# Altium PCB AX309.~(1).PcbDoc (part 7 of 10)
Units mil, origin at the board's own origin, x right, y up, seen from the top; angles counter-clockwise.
Board outline 5185 x 3614 mil, 4 copper layers (Top Layer, GND, Mid-Layer 1, Bottom Layer); 191 components, 352 nets, 1106 pads, 425 vias.
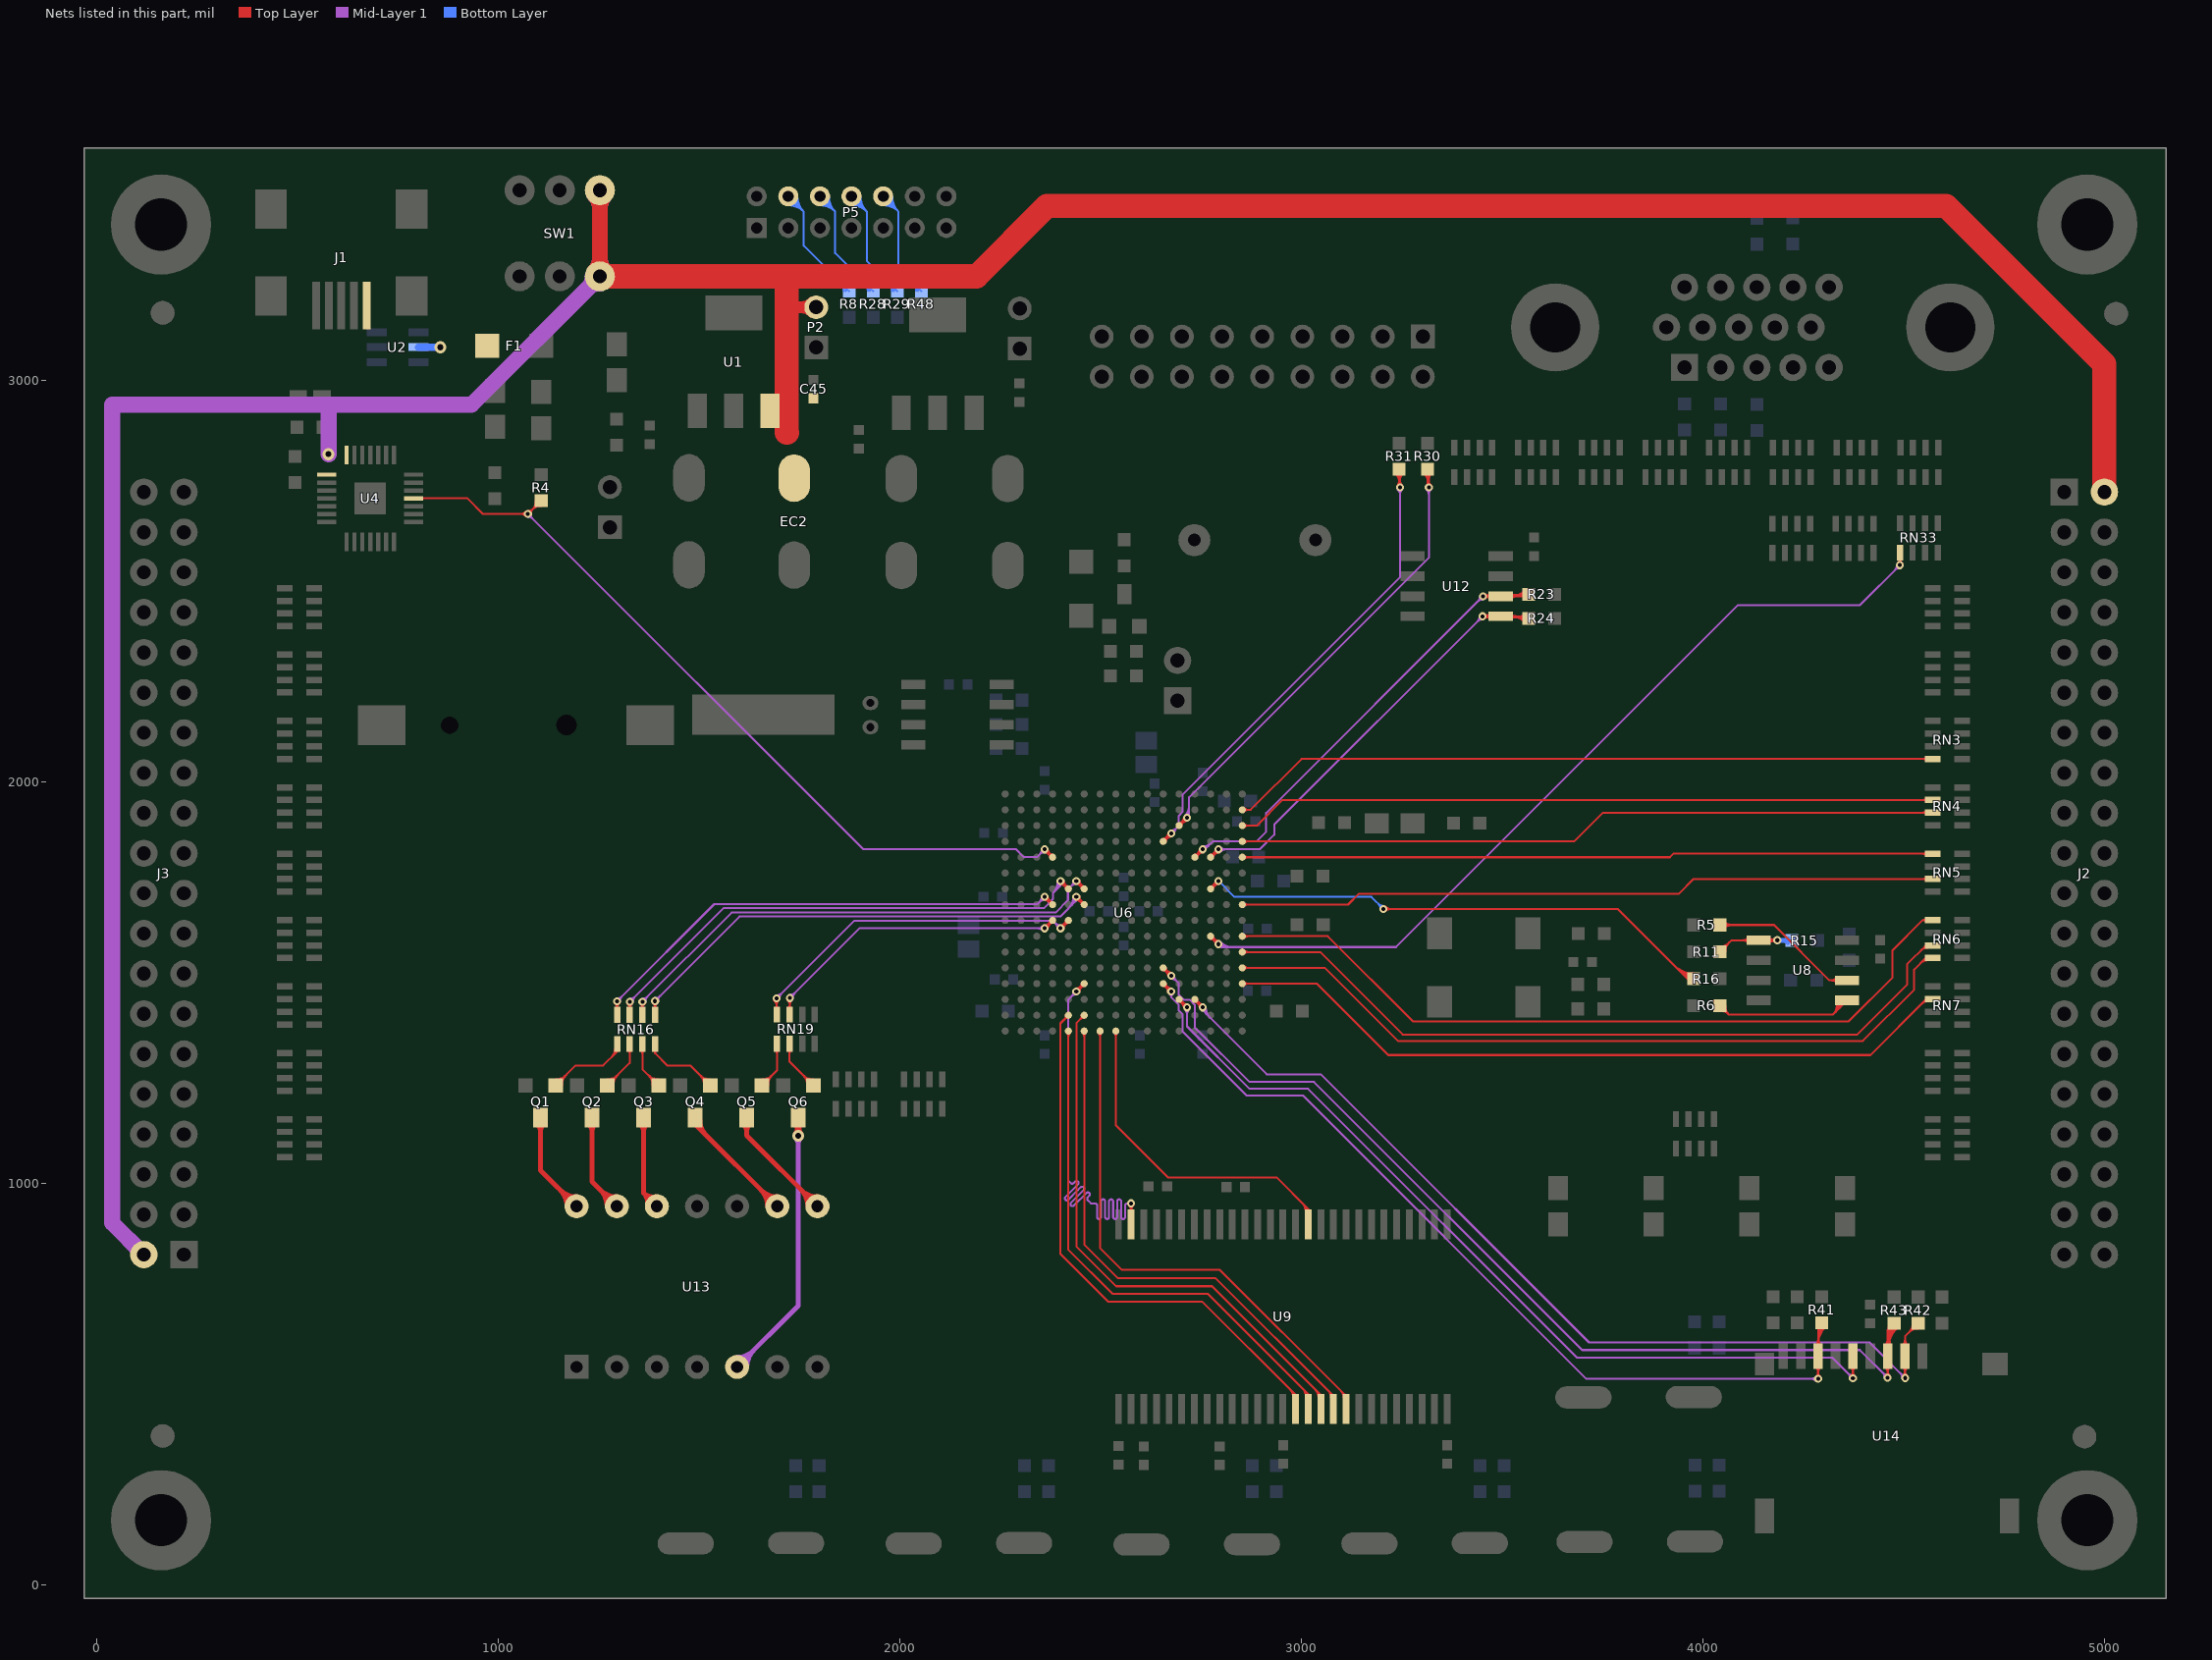
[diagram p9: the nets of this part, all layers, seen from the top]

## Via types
v1: diameter 20, hole 10, Top Layer to Bottom Layer, 328 vias
v2: diameter 30, hole 15, Top Layer to Bottom Layer, 95 vias
v3: diameter 40, hole 20, Top Layer to Bottom Layer, 2 vias

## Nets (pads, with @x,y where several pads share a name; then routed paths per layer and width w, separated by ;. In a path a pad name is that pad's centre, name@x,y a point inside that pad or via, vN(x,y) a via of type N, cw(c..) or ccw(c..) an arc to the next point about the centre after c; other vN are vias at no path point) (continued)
S_DB15: U6.F4 U9.53 | length 1558.9
  Top Layer w5: v1@2438.88,1484.58 ccw(c2436.17,1504.56) U6.F4@2453.63,1494.48 ; v1@2439.55,1479.63 ccw(c2437.9,1491.79) 2448.53,1485.65 ; v1(2439.89,1477.15) U6.F4@2459.57,1496.83 ; v1@2439.89,1484.65 ccw(c2439.89,1502.76) 2452.69,1489.95 ccw(c2465.5,1477.15) v1@2447.39,1477.15 ; v1@2442.37,1476.81 cw(c2454.53,1475.16) 2448.39,1485.79 ; v1@2447.32,1476.14 cw(c2467.3,1473.43) U6.F4@2457.22,1490.89 ; 2449.65,1487.6 cw(c2443.67,1491.05) v1@2441.86,1484.39 ; 2450.34,1486.91 ccw(c2453.79,1480.93) v1@2447.13,1479.12 ; U6.F4@2453.22,1496.83 cw(c2437.87,1496.83) 2448.72,1485.98 cw(c2459.57,1475.13) U6.F4@2459.57,1490.48 ; v1@2571.19,944.2 cw(c2558.39,931.4) 2576.5,931.4 cw(c2594.6,931.4) v1@2581.8,944.2 ; U9.53@2572.25,930.24 ccw(c2562.01,940.49) 2576.5,940.49 ccw(c2590.98,940.49) U9.53@2580.74,930.24 ; v1@2572.86,942.94 cw(c2568.3,934.71) 2577.39,937.15 cw(c2582.16,938.43) v1@2579.91,942.83 ; v1@2573.08,942.83 cw(c2570.83,938.43) 2575.6,937.15 cw(c2584.69,934.71) v1@2580.13,942.94 ; U9.53@2576.5,897 v1(2576.5,949.5) ; v1@2441.83,1484.39 ccw(c2443.66,1491.22) 2447.19,1485.1 cw(c2443.66,1491.22) v1@2441.83,1484.39 ; v1@2447.13,1479.09 cw(c2453.96,1480.92) 2447.84,1484.45 ccw(c2453.96,1480.92) v1@2447.13,1479.09
  Mid-Layer 1 w5: v1@2432.39,1477.15 cw(c2414.28,1477.15) 2427.09,1464.35 cw(c2439.89,1451.54) v1@2439.89,1469.65 ; v1(2439.89,1477.15) 2420.2,1457.46 2420.2,1005.8 2426,1000 ccw(c2429.54,1003.54) 2433.07,1000 2436.74,1003.67 cw(c2440.28,1000.13) 2443.81,1003.67 cw(c2440.28,1000.13) 2443.81,996.6 2412.67,965.46 ccw(c2416.21,961.92) 2412.67,958.39 ccw(c2416.21,961.92) 2419.74,958.39 2443.68,982.32 2450.88,989.53 cw(c2454.42,985.99) 2457.95,989.53 cw(c2454.42,985.99) 2457.95,982.46 2450.75,975.25 2426.69,951.19 ccw(c2430.22,947.66) 2426.69,944.12 ccw(c2430.22,947.66) 2433.76,944.12 2465.03,975.39 cw(c2468.56,971.85) 2472.1,975.39 cw(c2468.56,971.85) 2472.1,968.32 2468.43,964.64 ccw(c2471.96,961.11) 2468.43,957.57 2476.5,949.5 2486.5,949.5 cw(c2486.5,944.5) 2491.5,944.5 2491.5,915.48 ccw(c2496.5,915.48) 2496.5,910.48 ccw(c2496.5,915.48) 2501.5,915.48 2501.5,954.53 cw(c2506.5,954.53) 2506.5,959.53 cw(c2506.5,954.53) 2511.5,954.53 2511.5,915.48 ccw(c2516.5,915.48) 2516.5,910.48 ccw(c2516.5,915.48) 2521.5,915.48 2521.5,954.53 cw(c2526.5,954.53) 2526.5,959.53 cw(c2526.5,954.53) 2531.5,954.53 2531.5,915.48 ccw(c2536.5,915.48) 2536.5,910.48 ccw(c2536.5,915.48) 2541.5,915.48 2541.5,954.53 cw(c2546.5,954.53) 2546.5,959.53 cw(c2546.5,954.53) 2551.5,954.53 2551.5,915.48 ccw(c2556.5,915.48) 2556.5,910.48 ccw(c2556.5,915.48) 2561.5,915.48 2561.5,944.5 cw(c2566.5,944.5) 2566.5,949.5 v1(2576.5,949.5)
S_DQM0: U6.E2 U9.15 | length 1429.6
  Top Layer w5: U6.E2@2413.85,1418.09 cw(c2398.5,1418.09) 2409.35,1407.24 cw(c2420.2,1396.39) U6.E2@2420.2,1411.74 ; U6.E2@2420.2,1418.09 2400,1397.89 2400,824 2520,704 2754,704 2985.94,472.06 U9.15@2985.94,437 ; 2971.42,486.58 cw(c2950.84,466) U9.15@2979.94,466 ; 2979.96,478.04 cw(c2967.91,466) U9.15@2984.94,466
S_DQM1: U6.H1 U9.39 | length 933.5
  Top Layer w5: U6.H1@2533.82,1374.23 cw(c2522.96,1363.37) 2538.32,1363.37 cw(c2553.67,1363.37) U6.H1@2542.81,1374.23 ; U6.H1@2538.32,1378.72 2538.32,1143.68 2668,1014 2939,1014 3017.44,935.56 ; 3000.44,952.56 cw(c2973.88,926) U9.39@3011.44,926 ; 3008.97,944.03 cw(c2990.95,926) U9.39@3016.44,926 ; U9.39@3014.83,931.4 ccw(c3012.83,935.56) 3017.44,935.56 ; U9.39@3017.44,897 3017.44,935.56 ; 3017.51,935.49 cw(c3008.02,926) U9.39@3021.44,926 ; U9.39@3020.05,931.4 cw(c3022.06,935.56) 3017.44,935.56
S_NCAS: U6.F2 U9.17 | length 1441.8
  Top Layer w5: U6.F2@2453.22,1418.09 cw(c2437.87,1418.09) 2448.72,1407.24 cw(c2459.57,1396.39) U6.F2@2459.57,1411.74 ; U6.F2@2459.57,1418.09 2440,1398.52 2440,842 2539,743 2778,743 3048.94,472.06 U9.17@3048.94,437 ; 3034.41,486.59 cw(c3013.81,466) U9.17@3042.94,466 ; 3042.94,478.06 cw(c3030.89,466) U9.17@3047.94,466
S_NCS: U6.G1 U9.19 | length 1385.4
  Top Layer w5: U6.G1@2494.45,1374.23 cw(c2483.59,1363.37) 2498.94,1363.37 cw(c2514.3,1363.37) U6.G1@2503.44,1374.23 ; U6.G1@2498.94,1378.72 2498.94,838.06 2553.5,783.5 2797.5,783.5 U9.19@3111,470 ; 3099.52,481.49 cw(c3084.03,466) U9.19@3105.93,466 ; U9.19@3106.93,474.07 ccw(c3111.93,479.07) U9.19@3111.93,472 ; U9.19@3111,437.93 U9.19@3111,470 ; U9.19@3111.93,469.07 U9.19@3111,470
S_NRAS: U6.F1 U9.18 | length 1394.7
  Top Layer w5: U6.F1@2455.08,1374.23 cw(c2444.22,1363.37) 2459.57,1363.37 cw(c2474.92,1363.37) U6.F1@2464.07,1374.23 ; U6.F1@2459.57,1378.72 2459.57,847.43 2544,763 2787,763 3079,471 U9.18@3079,438.43 ; 3067.67,482.33 cw(c3051.34,466) U9.18@3074.43,466 ; U9.18@3076.2,473.8 cw(c3068.41,466) U9.18@3079.43,466 ; U9.18@3076.28,473.72 ccw(c3080.43,477.87) U9.18@3080.43,472
S_NWE: U6.E1 U9.16 | length 1406
  Top Layer w5: U6.E1@2415.71,1374.23 cw(c2404.85,1363.37) 2420.2,1363.37 cw(c2435.55,1363.37) U6.E1@2424.7,1374.23 ; U6.E1@2420.2,1378.72 2420.2,833.8 2530,724 2768,724 3017.44,474.56 ; 3001.15,490.85 cw(c2976.29,466) U9.16@3011.44,466 ; 3009.68,482.32 cw(c2993.36,466) U9.16@3016.44,466 ; U9.16@3015.39,471.64 ccw(c3014.34,474.56) 3017.44,474.56 ; U9.16@3017.44,437 3017.44,474.56 ; U9.16@3019.49,471.64 cw(c3020.55,474.56) 3017.44,474.56
SCL: R23.2 U6.N12 U12.6 | length 1627.9
  Top Layer w5: U6.N12@2735.17,1811.8 v1(2754.85,1831.48) ; U6.N12@2735.17,1818.15 ccw(c2735.17,1833.5) 2746.02,1822.65 ccw(c2756.87,1811.8) U6.N12@2741.52,1811.8 ; U6.N12@2737.52,1817.74 ccw(c2727.44,1835.2) v1@2747.42,1832.49 ; U6.N12@2741.11,1814.15 cw(c2758.57,1804.07) v1@2755.86,1824.05 ; 2744.4,1821.72 ccw(c2740.95,1827.7) v1@2747.61,1829.51 ; 2745.09,1821.03 cw(c2751.07,1817.58) v1@2752.88,1824.24 ; 2746.21,1822.98 cw(c2756.84,1816.84) v1@2755.19,1829 ; 2746.35,1822.84 ccw(c2740.21,1833.47) v1@2752.37,1831.82 ; v1@2747.35,1831.48 cw(c2729.24,1831.48) 2742.05,1818.68 cw(c2754.85,1805.87) v1@2754.85,1823.98 ; v1(3453,2462) U12.6@3497,2462 R23.2@3567,2462 ; v1@3458.3,2456.7 cw(c3471.11,2443.89) 3471.11,2462 cw(c3471.11,2480.11) v1@3458.3,2467.3 ; v1@3458.6,2457.01 cw(c3464.25,2451.97) 3466.2,2459.28 cw(c3468.63,2468.32) v1@3459.95,2464.81 ; v1@3458.6,2466.99 ccw(c3464.25,2472.03) 3466.2,2464.72 ccw(c3468.63,2455.68) v1@3459.95,2459.19 ; U12.6@3472.28,2455.28 ccw(c3456.06,2439.07) 3456.06,2462 ccw(c3456.06,2484.93) U12.6@3472.28,2468.72 ; U12.6@3517.82,2465.51 ccw(c3525.37,2474.93) 3527.76,2463.1 ; U12.6@3520.94,2469.41 ccw(c3534.08,2485.79) 3538.23,2465.21 ; U12.6@3521.72,2455.28 cw(c3537.94,2439.07) 3537.94,2462 cw(c3537.94,2484.93) U12.6@3521.72,2468.72 ; U12.6@3522.34,2462 ccw(c3522.34,2511.66) R23.2@3557.45,2476.55 ; U12.6@3522.91,2456.75 cw(c3537.89,2446.8) 3534.33,2464.42 ; 3534.41,2462 ccw(c3534.41,2499.59) R23.2@3560.99,2473.01 ; R23.2@3557.45,2457.45 ccw(c3546.48,2446.48) 3546.48,2462 ccw(c3546.48,2487.52) R23.2@3564.53,2469.47 ; v1@2752.91,1824.24 ccw(c2751.08,1817.41) 2747.55,1823.53 cw(c2751.08,1817.41) v1@2752.91,1824.24 ; 2746.9,1824.18 ccw(c2740.78,1827.71) 2747.61,1829.54 cw(c2740.78,1827.71) 2746.9,1824.18
  Mid-Layer 1 w5: v1(2754.85,1831.48) 2760.48,1831.48 2781,1852 2890,1852 2913,1875 2913,1922 v1(3453,2462) ; v1@2754.85,1833.98 ccw(c2754.85,1853.61) 2768.73,1839.73 ; v1@2754.85,1838.98 ccw(c2754.85,1870.68) 2777.27,1848.27 ; v1@3445.5,2462 cw(c3427.39,2462) 3440.2,2449.2 cw(c3453,2436.39) v1@3453,2454.5
SD_CLK: U6.M3 U14.5 | length 2425.1
  Top Layer w5: U6.M3@2695.8,1451.11 cw(c2695.8,1435.76) 2706.65,1446.61 cw(c2717.5,1457.46) U6.M3@2702.15,1457.46 ; U6.M3@2695.8,1457.46 v1(2715.48,1437.78) ; U6.M3@2698.15,1451.52 cw(c2688.07,1434.06) v1@2708.05,1436.77 ; U6.M3@2701.74,1455.11 ccw(c2719.2,1465.19) v1@2716.49,1445.21 ; 2705.03,1447.54 cw(c2701.58,1441.56) v1@2708.24,1439.75 ; 2705.72,1448.23 ccw(c2711.7,1451.68) v1@2713.51,1445.02 ; 2706.84,1446.28 ccw(c2717.47,1452.42) v1@2715.82,1440.26 ; 2706.98,1446.42 cw(c2700.84,1435.79) v1@2713,1437.44 ; v1@2707.98,1437.78 ccw(c2689.87,1437.78) 2702.68,1450.58 ccw(c2715.48,1463.39) v1@2715.48,1445.28 ; U14.5@4367.77,542.55 cw(c4351.88,526.66) 4374.35,526.66 cw(c4396.83,526.66) U14.5@4380.94,542.55 ; v1@4369.05,518.95 ccw(c4356.25,531.75) 4374.35,531.75 ccw(c4392.46,531.75) v1@4379.66,518.95 ; v1(4374.35,513.65) U14.5@4374.35,568.82 ; 2707.53,1445.08 cw(c2701.41,1441.55) 2708.24,1439.72 ccw(c2701.41,1441.55) 2707.53,1445.08 ; 2708.18,1445.73 ccw(c2711.71,1451.85) 2713.54,1445.02 cw(c2711.71,1451.85) 2708.18,1445.73
  Mid-Layer 1 w5: v1@2710.18,1432.48 cw(c2697.37,1419.67) 2715.48,1419.67 cw(c2733.59,1419.67) v1@2720.78,1432.48 ; v1(2715.48,1437.78) 2715.48,1390.52 2871,1235 3017,1235 3687,565 4323,565 v1(4374.35,513.65) ; v1@4366.85,513.65 ccw(c4348.75,513.65) 4361.55,526.45 ccw(c4374.35,539.25) v1@4374.35,521.15
SD_DIN: R43.2 U6.L5 U14.3 | length 3086.1
  Top Layer w5: U6.L5@2656.43,1529.85 cw(c2656.43,1514.5) 2667.28,1525.35 cw(c2678.13,1536.2) U6.L5@2662.78,1536.2 ; U6.L5@2656.43,1536.2 v1(2676.11,1516.52) ; U6.L5@2658.78,1530.26 cw(c2648.7,1512.8) v1@2668.68,1515.51 ; U6.L5@2662.37,1533.85 ccw(c2679.83,1543.93) v1@2677.12,1523.95 ; 2665.66,1526.28 cw(c2662.21,1520.3) v1@2668.87,1518.49 ; 2666.35,1526.97 ccw(c2672.33,1530.42) v1@2674.14,1523.76 ; 2667.47,1525.02 ccw(c2678.1,1531.16) v1@2676.45,1519 ; 2667.61,1525.16 cw(c2661.47,1514.53) v1@2673.63,1516.18 ; v1@2668.61,1516.52 ccw(c2650.5,1516.52) 2663.31,1529.32 ccw(c2676.11,1542.13) v1@2676.11,1524.02 ; U14.3@4454.39,542.55 cw(c4438.49,526.66) 4460.97,526.66 cw(c4483.45,526.66) U14.3@4467.55,542.55 ; U14.3@4454.39,595.09 ccw(c4438.49,610.98) 4460.97,610.98 ccw(c4483.45,610.98) U14.3@4467.55,595.09 ; U14.3@4455.5,596.04 ccw(c4443.31,612.81) 4463.79,609.56 ; v1@4455.67,520.27 ccw(c4442.86,533.08) 4460.97,533.08 ccw(c4479.08,533.08) v1@4466.27,520.27 ; U14.3@4455.87,596.3 ccw(c4440.2,620.26) 4468.22,614.39 ; U14.3@4458.61,592.11 ccw(c4449.55,605.97) 4465.75,602.58 ; v1(4460.97,514.97) U14.3@4460.97,568.82 4460.97,634.97 ; U14.3@4460.97,579.71 cw(c4548.29,579.71) R43.2@4486.55,641.45 ; U14.3@4460.97,591.78 cw(c4536.22,591.78) R43.2@4483.01,644.99 ; 4460.97,603.85 cw(c4524.15,603.85) R43.2@4479.47,648.53 ; 4460.97,615.92 cw(c4512.08,615.92) R43.2@4475.94,652.06 ; 4460.97,627.99 cw(c4500.01,627.99) R43.2@4472.4,655.6 ; R43.2@4464.06,647.16 cw(c4452.28,643.66) 4460.97,634.97 ; 4464.17,612.01 ccw(c4488.1,608.22) U14.3@4468.5,593.98 ; 4466.44,605.88 ccw(c4482.43,602.54) U14.3@4468.76,593.6 ; R43.2@4473.16,638.06 ccw(c4469.66,626.28) 4460.97,634.97 ; R43.2@4477,651 4460.97,634.97 ; v1@2674.17,1523.76 cw(c2672.34,1530.59) 2668.81,1524.47 ccw(c2672.34,1530.59) v1@2674.17,1523.76 ; 2668.16,1523.82 cw(c2662.04,1520.29) 2668.87,1518.46 ccw(c2662.04,1520.29) 2668.16,1523.82
  Mid-Layer 1 w5: v1@2676.11,1509.02 cw(c2676.11,1490.91) 2688.91,1503.72 cw(c2701.72,1516.52) v1@2683.61,1516.52 ; v1(2676.11,1516.52) 2695,1497.63 2695,1469 2707,1457 2722.17,1457 2735.17,1444 2735.17,1387.83 2871,1252 3032,1252 3700,584 4391.94,584 v1(4460.97,514.97) ; v1@4453.47,514.97 ccw(c4435.36,514.97) 4448.17,527.77 ccw(c4460.97,540.58) v1@4460.97,522.47
SD_DOUT: R41.2 U6.L4 U14.7 | length 2709
  Top Layer w5: U6.L4@2656.43,1490.48 cw(c2656.43,1475.13) 2667.28,1485.98 cw(c2678.13,1496.83) U6.L4@2662.78,1496.83 ; U6.L4@2656.43,1496.83 v1(2676,1477.26) ; U6.L4@2658.8,1490.87 cw(c2648.87,1473.67) v1@2668.56,1476.28 ; U6.L4@2662.39,1494.46 ccw(c2679.59,1504.39) v1@2676.98,1484.69 ; 2665.68,1486.9 cw(c2662.34,1481.1) v1@2668.78,1479.29 ; 2666.36,1487.58 ccw(c2672.16,1490.92) v1@2673.97,1484.48 ; 2667.46,1485.67 ccw(c2677.91,1491.7) v1@2676.33,1479.74 ; 2667.59,1485.8 cw(c2661.56,1475.35) v1@2673.52,1476.93 ; v1@2668.5,1477.26 ccw(c2650.39,1477.26) 2663.2,1490.06 ccw(c2676,1502.87) v1@2676,1484.76 ; U14.7@4281.16,542.55 cw(c4265.26,526.66) 4287.74,526.66 cw(c4310.22,526.66) U14.7@4294.32,542.55 ; U14.7@4281.16,595.09 ccw(c4265.26,610.98) 4287.74,610.98 ccw(c4310.22,610.98) U14.7@4294.32,595.09 ; U14.7@4282.16,595.96 ccw(c4271.17,610.63) 4289.32,608.02 ; v1@4282.44,517.56 ccw(c4269.63,530.37) 4287.74,530.37 ccw(c4305.85,530.37) v1@4293.04,517.56 ; v1(4287.74,512.26) U14.7@4287.74,568.82 4287.74,642.74 R41.2@4297,652 ; U14.7@4287.74,597.05 cw(c4351.95,597.05) R41.2@4306.55,642.45 ; 4287.74,609.12 cw(c4339.88,609.12) R41.2@4303.01,645.99 ; 4287.74,621.19 cw(c4327.81,621.19) R41.2@4299.47,649.53 ; 4287.74,633.27 cw(c4315.73,633.27) R41.2@4295.94,653.06 ; 4288.22,600.41 ccw(c4299.28,598.82) U14.7@4290.95,591.38 ; 4289.75,611.03 ccw(c4309.71,608.16) U14.7@4294.68,594.71 ; 2668.04,1484.67 cw(c2661.79,1481.07) 2668.76,1479.2 ccw(c2661.79,1481.07) 2668.04,1484.67 ; 2668.59,1485.22 ccw(c2672.19,1491.47) 2674.06,1484.5 cw(c2672.19,1491.47) 2668.59,1485.22
  Mid-Layer 1 w5: v1@2671.79,1471.06 cw(c2666.24,1462.89) 2676.11,1462.89 ; v1@2676.11,1477.15 2676.11,1462.89 ; v1@2680.36,1471.16 ccw(c2686.28,1462.89) 2676.11,1462.89 ; v1@4282.44,506.96 ccw(c4269.63,494.15) 4269.63,512.26 ccw(c4269.63,530.37) v1@4282.44,517.56 ; v1(4287.74,512.26) 3710.74,512.26 3005,1218 2864,1218 2705,1377 2705,1420 2695,1430 2695,1444 2676.11,1462.89
SD_NCS: R42.2 U6.N3 U14.2 | length 2725.4
  Top Layer w5: U6.N3@2735.17,1451.11 cw(c2735.17,1435.76) 2746.02,1446.61 cw(c2756.87,1457.46) U6.N3@2741.52,1457.46 ; U6.N3@2735.17,1457.46 v1(2754.85,1437.78) ; U6.N3@2737.52,1451.52 cw(c2727.44,1434.06) v1@2747.42,1436.77 ; U6.N3@2741.11,1455.11 ccw(c2758.57,1465.19) v1@2755.86,1445.21 ; 2744.4,1447.54 cw(c2740.95,1441.56) v1@2747.61,1439.75 ; 2745.09,1448.23 ccw(c2751.07,1451.68) v1@2752.88,1445.02 ; 2746.21,1446.28 ccw(c2756.84,1452.42) v1@2755.19,1440.26 ; 2746.35,1446.42 cw(c2740.21,1435.79) v1@2752.37,1437.44 ; v1@2747.35,1437.78 ccw(c2729.24,1437.78) 2742.05,1450.58 ccw(c2754.85,1463.39) v1@2754.85,1445.28 ; U14.2@4497.69,542.55 cw(c4481.8,526.66) 4504.28,526.66 cw(c4526.75,526.66) U14.2@4510.86,542.55 ; U14.2@4497.69,595.09 ccw(c4481.8,610.98) 4504.28,610.98 ccw(c4526.75,610.98) U14.2@4510.86,595.09 ; v1@4498.97,519.58 ccw(c4486.17,532.38) 4504.28,532.38 ccw(c4522.38,532.38) v1@4509.58,519.58 ; v1(4504.28,514.28) U14.2@4504.28,568.82 4504.28,618.28 R42.2@4537,651 ; R42.2@4523.5,651 cw(c4490.91,651) 4513.95,627.95 cw(c4537,604.91) R42.2@4537,637.5 ; R42.2@4528.5,651 cw(c4507.98,651) 4522.49,636.49 cw(c4537,621.98) R42.2@4537,642.5 ; v1@2752.91,1445.02 cw(c2751.08,1451.85) 2747.55,1445.73 ccw(c2751.08,1451.85) v1@2752.91,1445.02 ; 2746.9,1445.08 cw(c2740.78,1441.55) 2747.61,1439.72 ccw(c2740.78,1441.55) 2746.9,1445.08
  Mid-Layer 1 w5: v1(2754.85,1437.78) 2754.85,1430.15 2914,1271 3049,1271 3717,603 4415.55,603 v1(4504.28,514.28) ; v1@2757.35,1437.78 ccw(c2781.81,1437.78) 2764.51,1420.49 ; v1@2762.35,1437.78 ccw(c2798.88,1437.78) 2773.05,1411.95 ; v1@4496.78,514.28 ccw(c4478.67,514.28) 4491.47,527.08 ccw(c4504.28,539.88) v1@4504.28,521.78
SDA: R24.2 U6.P12 U12.5 | length 1547.9
  Top Layer w5: U6.P12@2774.54,1811.8 v1(2794.22,1831.48) ; U6.P12@2774.54,1818.15 ccw(c2774.54,1833.5) 2785.39,1822.65 ccw(c2796.24,1811.8) U6.P12@2780.89,1811.8 ; U6.P12@2776.89,1817.74 ccw(c2766.81,1835.2) v1@2786.79,1832.49 ; U6.P12@2780.48,1814.15 cw(c2797.94,1804.07) v1@2795.23,1824.05 ; 2783.77,1821.72 ccw(c2780.32,1827.7) v1@2786.98,1829.51 ; 2784.46,1821.03 cw(c2790.44,1817.58) v1@2792.25,1824.24 ; 2785.58,1822.98 cw(c2796.21,1816.84) v1@2794.56,1829 ; 2785.72,1822.84 ccw(c2779.58,1833.47) v1@2791.74,1831.82 ; v1@2786.72,1831.48 cw(c2768.61,1831.48) 2781.42,1818.68 cw(c2794.22,1805.87) v1@2794.22,1823.98 ; v1(3452,2412) U12.5@3497,2412 3562,2412 R24.2@3567,2407 ; v1@3457.3,2406.7 cw(c3470.11,2393.89) 3470.11,2412 cw(c3470.11,2430.11) v1@3457.3,2417.3 ; v1@3457.57,2406.97 cw(c3463.65,2401.48) 3465.77,2409.4 cw(c3468.59,2419.9) v1@3458.77,2415.22 ; v1@3457.57,2417.03 ccw(c3463.65,2422.52) 3465.77,2414.6 ccw(c3468.59,2404.1) v1@3458.77,2408.78 ; U12.5@3472.28,2405.28 ccw(c3456.06,2389.07) 3456.06,2412 ccw(c3456.06,2434.93) U12.5@3472.28,2418.72 ; U12.5@3517.82,2408.49 cw(c3525.37,2399.07) 3527.76,2410.9 ; U12.5@3520.94,2404.59 cw(c3534.08,2388.21) 3538.23,2408.79 ; U12.5@3521.72,2405.28 cw(c3537.94,2389.07) 3537.94,2412 cw(c3537.94,2434.93) U12.5@3521.72,2418.72 ; U12.5@3522.34,2412 cw(c3522.34,2362.34) R24.2@3557.45,2397.45 ; U12.5@3522.91,2417.25 ccw(c3537.89,2427.2) 3534.33,2409.58 ; 3534.41,2412 cw(c3534.41,2374.41) R24.2@3560.99,2400.99 ; R24.2@3557.45,2416.55 cw(c3546.48,2427.52) 3546.48,2412 cw(c3546.48,2386.48) R24.2@3564.53,2404.53 ; 2786.27,1824.18 ccw(c2780.15,1827.71) 2786.98,1829.54 cw(c2780.15,1827.71) 2786.27,1824.18 ; 2786.92,1823.53 cw(c2790.45,1817.41) 2792.28,1824.24 ccw(c2790.45,1817.41) 2786.92,1823.53
  Mid-Layer 1 w5: v1(2794.22,1831.48) 2896.48,1831.48 2933,1868 2933,1893 v1(3452,2412) ; v1@2799.52,1826.18 cw(c2812.33,1813.37) 2812.33,1831.48 cw(c2812.33,1849.59) v1@2799.52,1836.78 ; v1@3444.5,2412 cw(c3426.39,2412) 3439.2,2399.2 cw(c3452,2386.39) v1@3452,2404.5
SEL0: RN16.8 U6.D9 | length 1517
  Top Layer w5: v1@1290.7,1447.7 cw(c1277.89,1434.89) 1296,1434.89 cw(c1314.11,1434.89) v1@1301.3,1447.7 ; RN16.8@1292.2,1434.76 ccw(c1283.03,1443.93) 1296,1443.93 ccw(c1308.97,1443.93) RN16.8@1299.8,1434.76 ; v1@1292.67,1446.28 cw(c1289.25,1439.38) 1296.69,1441.37 cw(c1300.58,1442.42) v1@1298.98,1446.12 ; v1@1293.02,1446.12 cw(c1291.42,1442.42) 1295.31,1441.37 cw(c1302.75,1439.38) v1@1299.33,1446.28 ; RN16.8@1296,1419.15 v1(1296,1453) ; v1@2360.14,1705.94 cw(c2357.43,1685.96) U6.D9@2374.89,1696.04 ; v1@2360.81,1710.89 cw(c2359.16,1698.73) 2369.79,1704.87 ; v1@2361.15,1705.87 cw(c2361.15,1687.76) 2373.95,1700.57 cw(c2386.76,1713.37) v1@2368.65,1713.37 ; v1(2361.15,1713.37) U6.D9@2380.83,1693.68 ; v1@2363.63,1713.71 ccw(c2375.79,1715.36) 2369.65,1704.73 ; v1@2368.39,1711.4 ccw(c2375.05,1709.59) 2371.6,1703.61 ; v1@2368.58,1714.38 ccw(c2388.56,1717.09) U6.D9@2378.48,1699.63 ; 2370.91,1702.92 ccw(c2364.93,1699.47) v1@2363.12,1706.13 ; U6.D9@2374.48,1693.68 ccw(c2359.13,1693.68) 2369.98,1704.54 ccw(c2380.83,1715.39) U6.D9@2380.83,1700.04 ; v1@2363.09,1706.13 cw(c2364.92,1699.3) 2368.45,1705.42 ccw(c2364.92,1699.3) v1@2363.09,1706.13 ; v1@2368.39,1711.43 ccw(c2375.22,1709.6) 2369.1,1706.07 cw(c2375.22,1709.6) v1@2368.39,1711.43
  Mid-Layer 1 w5: v1(1296,1453) 1538,1695 2342.78,1695 v1(2361.15,1713.37) ; v1@1296,1460.5 ccw(c1296,1478.61) 1308.8,1465.8 ccw(c1321.61,1453) v1@1303.5,1453 ; v1@2353.65,1713.37 cw(c2335.54,1713.37) 2348.35,1700.57 cw(c2361.15,1687.76) v1@2361.15,1705.87
SEL0_T: Q1.1 RN16.1 | length 339.2
  Top Layer w5: Q1.1@1143,1243 1193,1293 1261,1293 1296,1328 RN16.1@1296,1346 ; Q1.1@1143,1253.5 ccw(c1143,1278.85) 1160.92,1260.92 ccw(c1178.85,1243) Q1.1@1153.5,1243 ; Q1.1@1143,1258.5 ccw(c1143,1295.92) 1169.46,1269.46 ccw(c1195.92,1243) Q1.1@1158.5,1243 ; 1282.45,1314.45 ccw(c1262.71,1334.19) RN16.1@1290.63,1334.19 ; 1290.99,1322.99 ccw(c1279.78,1334.19) RN16.1@1295.63,1334.19
SEL0_TT: Q1.3 U13.14 | length 394.8
  Top Layer w12: Q1.3@1096.51,1147.51 cw(c1076.03,1127.03) 1105,1127.03 cw(c1133.97,1127.03) Q1.3@1113.49,1147.51 ; Q1.3@1105,1163 1105,1032 U13.14@1195,942 ; U13.14@1171,942 ccw(c1113.06,942) 1154.03,982.97 ccw(c1195,1023.94) U13.14@1195,966
SEL1: RN16.7 U6.E10 | length 1606
  Top Layer w5: v1@1322.19,1446.2 cw(c1309.39,1433.4) 1327.5,1433.4 cw(c1345.6,1433.4) v1@1332.8,1446.2 ; RN16.7@1323.7,1434.76 ccw(c1314.52,1443.93) 1327.5,1443.93 ccw(c1340.47,1443.93) RN16.7@1331.3,1434.76 ; v1@1324.72,1444.54 cw(c1323.54,1441.56) 1326.64,1440.73 cw(c1331.92,1439.31) v1@1330.06,1444.45 ; v1@1324.94,1444.45 cw(c1323.07,1439.31) 1328.36,1440.73 cw(c1331.45,1441.56) v1@1330.27,1444.54 ; RN16.7@1327.5,1419.15 v1(1327.5,1451.5) ; v1@2399.51,1745.31 cw(c2396.8,1725.33) U6.E10@2414.26,1735.41 ; v1@2400.18,1750.26 cw(c2398.53,1738.1) 2409.16,1744.24 ; v1@2400.52,1745.24 cw(c2400.52,1727.13) 2413.32,1739.94 cw(c2426.13,1752.74) v1@2408.02,1752.74 ; v1(2400.52,1752.74) U6.E10@2420.2,1733.06 ; v1@2402.49,1745.5 cw(c2404.3,1738.84) 2410.28,1742.29 ; v1@2403,1753.08 ccw(c2415.16,1754.73) 2409.02,1744.1 ; v1@2407.76,1750.77 ccw(c2414.42,1748.96) 2410.97,1742.98 ; v1@2407.95,1753.75 ccw(c2427.93,1756.46) U6.E10@2417.85,1739 ; U6.E10@2413.85,1733.06 ccw(c2398.5,1733.06) 2409.35,1743.91 ccw(c2420.2,1754.76) U6.E10@2420.2,1739.41 ; v1@2402.46,1745.5 cw(c2404.29,1738.67) 2407.82,1744.79 ccw(c2404.29,1738.67) v1@2402.46,1745.5 ; v1@2407.76,1750.8 ccw(c2414.59,1748.97) 2408.47,1745.44 cw(c2414.59,1748.97) v1@2407.76,1750.8
  Mid-Layer 1 w5: v1(1327.5,1451.5) 1560.99,1685 2359,1685 2381.78,1707.78 2381.78,1722.78 ; v1@1327.5,1459 ccw(c1327.5,1477.11) 1340.3,1464.31 ccw(c1353.1,1451.5) v1@1335,1451.5 ; 2389.67,1730.67 ccw(c2369.38,1750.95) v1@2398.02,1752.6 ; v1@2393.03,1752.31 cw(c2354.46,1750.1) 2381.78,1722.78 ; 2397.55,1738.55 ccw(c2384.3,1751.81) v1@2403.01,1752.88 ; v1@2397.65,1745.81 cw(c2395.87,1741.52) 2400.52,1741.52 ; v1(2400.52,1752.74) 2400.52,1741.52 ; v1@2403.39,1745.81 ccw(c2405.16,1741.52) 2400.52,1741.52 ; 2381.78,1722.78 2400.52,1741.52
SEL1_T: Q2.1 RN16.2 | length 245.2
  Top Layer w5: Q2.1@1271.4,1243 1327.5,1299.1 RN16.2@1327.5,1346 ; Q2.1@1271.4,1253.5 ccw(c1271.4,1278.85) 1289.32,1260.92 ccw(c1307.25,1243) Q2.1@1281.9,1243 ; Q2.1@1271.4,1258.5 ccw(c1271.4,1295.92) 1297.86,1269.46 ccw(c1324.32,1243) Q2.1@1286.9,1243 ; RN16.2@1323.7,1330.39 cw(c1314.52,1321.22) 1327.5,1321.22 cw(c1340.47,1321.22) RN16.2@1331.3,1330.39
SEL1_TT: Q2.3 U13.13 | length 383
  Top Layer w12: Q2.3@1224.91,1147.51 cw(c1204.43,1127.03) 1233.4,1127.03 cw(c1262.37,1127.03) Q2.3@1241.89,1147.51 ; Q2.3@1233.4,1163 1233.4,1003.6 U13.13@1295,942 ; U13.13@1271,942 ccw(c1213.06,942) 1254.03,982.97 ccw(c1295,1023.94) U13.13@1295,966
SEL2: RN16.6 U6.F10 | length 1561.1
  Top Layer w5: v1@1353.69,1446.69 cw(c1340.89,1433.89) 1358.99,1433.89 cw(c1377.1,1433.89) v1@1364.3,1446.69 ; RN16.6@1355.19,1434.76 ccw(c1346.02,1443.93) 1358.99,1443.93 ccw(c1371.97,1443.93) RN16.6@1362.79,1434.76 ; RN16.6@1358.99,1419.15 v1(1358.99,1451.99) ; v1@1361.81,1445.04 ccw(c1364.13,1439.35) 1358.19,1440.94 ccw(c1354.83,1441.84) 1356.15,1445.05 cw(c1353.85,1439.35) 1359.8,1440.94 cw(c1363.15,1441.84) v1@1361.83,1445.05 ; v1@2438.88,1745.31 cw(c2436.17,1725.33) U6.F10@2453.63,1735.41 ; v1@2439.55,1750.26 cw(c2437.9,1738.1) 2448.53,1744.24 ; v1@2439.89,1745.24 cw(c2439.89,1727.13) 2452.69,1739.94 cw(c2465.5,1752.74) v1@2447.39,1752.74 ; v1(2439.89,1752.74) U6.F10@2459.57,1733.06 ; v1@2442.37,1753.08 ccw(c2454.53,1754.73) 2448.39,1744.1 ; v1@2447.13,1750.77 ccw(c2453.79,1748.96) 2450.34,1742.98 ; v1@2447.32,1753.75 ccw(c2467.3,1756.46) U6.F10@2457.22,1739 ; 2449.65,1742.29 ccw(c2443.67,1738.84) v1@2441.86,1745.5 ; U6.F10@2453.22,1733.06 ccw(c2437.87,1733.06) 2448.72,1743.91 ccw(c2459.57,1754.76) U6.F10@2459.57,1739.41 ; v1@2441.83,1745.5 cw(c2443.66,1738.67) 2447.19,1744.79 ccw(c2443.66,1738.67) v1@2441.83,1745.5 ; v1@2447.13,1750.8 ccw(c2453.96,1748.97) 2447.84,1745.44 cw(c2453.96,1748.97) v1@2447.13,1750.8
  Mid-Layer 1 w5: v1(1358.99,1451.99) 1581,1674 2388,1674 2419,1705 2419,1731.85 v1(2439.89,1752.74) ; v1@1358.99,1459.49 ccw(c1358.99,1477.6) 1371.8,1464.8 ccw(c1384.6,1451.99) v1@1366.49,1451.99 ; v1@2432.39,1752.74 cw(c2414.28,1752.74) 2427.09,1739.94 cw(c2439.89,1727.13) v1@2439.89,1745.24
SEL2_T: Q3.1 RN16.3 | length 238.9
  Top Layer w5: RN16.3@1355.19,1330.39 cw(c1346.02,1321.22) 1358.99,1321.22 cw(c1371.97,1321.22) RN16.3@1362.79,1330.39 ; RN16.3@1358.99,1346 1358.99,1283.81 Q3.1@1399.8,1243 ; Q3.1@1384.3,1243 ccw(c1346.88,1243) 1373.34,1269.46 ccw(c1399.8,1295.92) Q3.1@1399.8,1258.5 ; Q3.1@1389.3,1243 ccw(c1363.95,1243) 1381.88,1260.92 ccw(c1399.8,1278.85) Q3.1@1399.8,1253.5
SEL2_TT: Q3.3 U13.12 | length 344.4
  Top Layer w12: Q3.3@1353.31,1147.51 cw(c1332.83,1127.03) 1361.8,1127.03 cw(c1390.77,1127.03) Q3.3@1370.29,1147.51 ; Q3.3@1361.8,1163 1361.8,975.2 ; U13.12@1371.31,945.82 ccw(c1337.82,951.21) 1361.8,975.2 ; U13.12@1391.18,965.69 cw(c1385.79,999.18) 1361.8,975.2 ; U13.12@1395,942 1361.8,975.2
SEL3: RN16.5 U6.F9 | length 1548.4
  Top Layer w5: v1@1385.18,1448.18 cw(c1372.38,1435.38) 1390.49,1435.38 cw(c1408.59,1435.38) v1@1395.79,1448.18 ; RN16.5@1386.69,1434.76 ccw(c1377.51,1443.93) 1390.49,1443.93 ccw(c1403.46,1443.93) RN16.5@1394.29,1434.76 ; v1@1386.93,1446.89 cw(c1382.87,1439.38) 1391.12,1441.59 cw(c1395.27,1442.7) v1@1393.53,1446.63 ; v1@1387.45,1446.63 cw(c1385.7,1442.7) 1389.86,1441.58 cw(c1398.1,1439.38) v1@1394.05,1446.89 ; RN16.5@1390.49,1419.15 v1(1390.49,1453.49) ; v1@2438.88,1705.94 cw(c2436.17,1685.96) U6.F9@2453.63,1696.04 ; v1@2439.55,1710.89 cw(c2437.9,1698.73) 2448.53,1704.87 ; v1@2439.89,1705.87 cw(c2439.89,1687.76) 2452.69,1700.57 cw(c2465.5,1713.37) v1@2447.39,1713.37 ; v1(2439.89,1713.37) U6.F9@2459.57,1693.68 ; v1@2442.37,1713.71 ccw(c2454.53,1715.36) 2448.39,1704.73 ; v1@2447.13,1711.4 ccw(c2453.79,1709.59) 2450.34,1703.61 ; v1@2447.32,1714.38 ccw(c2467.3,1717.09) U6.F9@2457.22,1699.63 ; 2449.65,1702.92 ccw(c2443.67,1699.47) v1@2441.86,1706.13 ; U6.F9@2453.22,1693.68 ccw(c2437.87,1693.68) 2448.72,1704.54 ccw(c2459.57,1715.39) U6.F9@2459.57,1700.04 ; v1@2441.83,1706.13 cw(c2443.66,1699.3) 2447.19,1705.42 ccw(c2443.66,1699.3) v1@2441.83,1706.13 ; v1@2447.13,1711.43 ccw(c2453.96,1709.6) 2447.84,1706.07 cw(c2453.96,1709.6) v1@2447.13,1711.43
  Mid-Layer 1 w5: v1(1390.49,1453.49) 1601,1664 2400,1664 2439.89,1703.89 v1(2439.89,1713.37) ; v1@1390.49,1460.99 ccw(c1390.49,1479.09) 1403.29,1466.29 ccw(c1416.09,1453.49) v1@1397.99,1453.49 ; 2420.38,1684.38 ccw(c2391.39,1713.37) v1@2432.39,1713.37 ; 2428.92,1692.92 ccw(c2408.46,1713.37) v1@2437.39,1713.37 ; 2437.45,1701.45 ccw(c2425.53,1713.37) v1@2442.39,1713.37
SEL3_T: Q4.1 RN16.4 | length 306.9
  Top Layer w5: RN16.4@1387.29,1329.87 cw(c1382.57,1323.51) 1390.49,1323.51 ; RN16.4@1390.49,1346 1390.49,1323.51 ; RN16.4@1393.69,1329.87 ccw(c1398.41,1323.51) 1390.49,1323.51 ; Q4.1@1512.7,1243 ccw(c1475.28,1243) 1501.74,1269.46 ccw(c1528.2,1295.92) Q4.1@1528.2,1258.5 ; Q4.1@1517.7,1243 ccw(c1492.35,1243) 1510.28,1260.92 ccw(c1528.2,1278.85) Q4.1@1528.2,1253.5 ; Q4.1@1528.2,1243 1478.6,1292.6 1421.4,1292.6 1390.49,1323.51
SEL3_TT: Q4.3 U13.9 | length 437
  Top Layer w12: Q4.3@1490.2,1163 1490.2,1146.8 U13.9@1695,942 ; Q4.3@1502.2,1156 ccw(c1553.38,1156) 1517.19,1119.81 ; U13.9@1671,942 ccw(c1613.06,942) 1654.03,982.97 ccw(c1695,1023.94) U13.9@1695,966
SEL4: RN19.8 U6.E8 | length 1119.5
  Top Layer w5: v1@1687.7,1454.7 cw(c1674.89,1441.89) 1693,1441.89 cw(c1711.11,1441.89) v1@1698.3,1454.7 ; RN19.8@1690.2,1435.76 ccw(c1683.44,1442.52) 1693,1442.52 ; RN19.8@1693,1421.15 v1(1693,1460) ; 1693,1447.35 ccw(c1709.39,1447.35) RN19.8@1697.8,1435.76 ; v1@2399.51,1642.06 ccw(c2396.8,1662.04) U6.E8@2414.26,1651.96 ; v1@2400.18,1637.11 ccw(c2398.53,1649.27) 2409.16,1643.13 ; v1(2400.52,1634.63) U6.E8@2420.2,1654.32 ; v1@2400.52,1642.13 ccw(c2400.52,1660.24) 2413.32,1647.43 ccw(c2426.13,1634.63) v1@2408.02,1634.63 ; v1@2402.49,1641.87 ccw(c2404.3,1648.53) 2410.28,1645.08 ; v1@2403,1634.29 cw(c2415.16,1632.64) 2409.02,1643.27 ; v1@2407.76,1636.6 cw(c2414.42,1638.41) 2410.97,1644.39 ; v1@2407.95,1633.62 cw(c2427.93,1630.91) U6.E8@2417.85,1648.37 ; U6.E8@2413.85,1654.32 cw(c2398.5,1654.32) 2409.35,1643.46 cw(c2420.2,1632.61) U6.E8@2420.2,1647.96 ; v1@2402.46,1641.87 ccw(c2404.29,1648.7) 2407.82,1642.58 cw(c2404.29,1648.7) v1@2402.46,1641.87 ; v1@2407.76,1636.57 cw(c2414.59,1638.4) 2408.47,1641.93 ccw(c2414.59,1638.4) v1@2407.76,1636.57
  Mid-Layer 1 w5: v1(1693,1460) 1886,1653 2382.15,1653 v1(2400.52,1634.63) ; v1@1693,1467.5 ccw(c1693,1485.61) 1705.8,1472.8 ccw(c1718.61,1460) v1@1700.5,1460 ; v1@2393.02,1634.63 ccw(c2374.91,1634.63) 2387.72,1647.43 ccw(c2400.52,1660.24) v1@2400.52,1642.13
SEL4_T: Q5.1 RN19.1 | length 238.5
  Top Layer w5: Q5.1@1656.6,1243 1694,1280.4 RN19.1@1694,1347 ; Q5.1@1656.6,1253.5 ccw(c1656.6,1278.85) 1674.52,1260.92 ccw(c1692.45,1243) Q5.1@1667.1,1243 ; Q5.1@1656.6,1258.5 ccw(c1656.6,1295.92) 1683.06,1269.46 ccw(c1709.52,1243) Q5.1@1672.1,1243 ; RN19.1@1690.2,1331.39 cw(c1681.03,1322.22) 1694,1322.22 cw(c1706.97,1322.22) RN19.1@1697.8,1331.39
SEL4_TT: Q5.3 U13.8 | length 430.6
  Top Layer w12: Q5.3@1610.11,1147.51 cw(c1589.63,1127.03) 1618.6,1127.03 cw(c1647.57,1127.03) Q5.3@1627.09,1147.51 ; Q5.3@1618.6,1163 1618.6,1118.4 U13.8@1795,942 ; U13.8@1771,942 ccw(c1713.06,942) 1754.03,982.97 ccw(c1795,1023.94) U13.8@1795,966
SEL5: RN19.7 U6.D8 | length 1033
  Top Layer w5: v1@1720.7,1455.7 cw(c1707.89,1442.89) 1726,1442.89 cw(c1744.11,1442.89) v1@1731.3,1455.7 ; RN19.7@1721.7,1435.76 ccw(c1711.31,1446.15) 1726,1446.15 ; RN19.7@1726,1420.65 v1(1726,1461) ; 1726,1443.72 ccw(c1737.25,1443.72) RN19.7@1729.3,1435.76 ; v1@2360.14,1642.06 ccw(c2357.43,1662.04) U6.D8@2374.89,1651.96 ; v1@2360.81,1637.11 ccw(c2359.16,1649.27) 2369.79,1643.13 ; v1(2361.15,1634.63) U6.D8@2380.83,1654.32 ; v1@2361.15,1642.13 ccw(c2361.15,1660.24) 2373.95,1647.43 ccw(c2386.76,1634.63) v1@2368.65,1634.63 ; v1@2363.63,1634.29 cw(c2375.79,1632.64) 2369.65,1643.27 ; v1@2368.39,1636.6 cw(c2375.05,1638.41) 2371.6,1644.39 ; v1@2368.58,1633.62 cw(c2388.56,1630.91) U6.D8@2378.48,1648.37 ; 2370.91,1645.08 cw(c2364.93,1648.53) v1@2363.12,1641.87 ; U6.D8@2374.48,1654.32 cw(c2359.13,1654.32) 2369.98,1643.46 cw(c2380.83,1632.61) U6.D8@2380.83,1647.96 ; v1@2363.09,1641.87 ccw(c2364.92,1648.7) 2368.45,1642.58 cw(c2364.92,1648.7) v1@2363.09,1641.87 ; v1@2368.39,1636.57 cw(c2375.22,1638.4) 2369.1,1641.93 ccw(c2375.22,1638.4) v1@2368.39,1636.57
  Mid-Layer 1 w5: v1(1726,1461) 1899.63,1634.63 v1(2361.15,1634.63) ; v1@1726,1468.5 ccw(c1726,1486.61) 1738.8,1473.8 ccw(c1751.61,1461) v1@1733.5,1461 ; v1@2355.85,1629.33 ccw(c2343.04,1616.52) 2343.04,1634.63 ccw(c2343.04,1652.74) v1@2355.85,1639.93
SEL5_T: Q6.1 RN19.2 | length 247.6
  Top Layer w5: RN19.2@1721.7,1331.39 cw(c1712.52,1322.22) 1725.5,1322.22 cw(c1738.47,1322.22) RN19.2@1729.3,1331.39 ; RN19.2@1725.5,1347 1725.5,1302.5 Q6.1@1785,1243 ; Q6.1@1769.5,1243 ccw(c1732.08,1243) 1758.54,1269.46 ccw(c1785,1295.92) Q6.1@1785,1258.5 ; Q6.1@1774.5,1243 ccw(c1749.15,1243) 1767.08,1260.92 ccw(c1785,1278.85) Q6.1@1785,1253.5
SEL5_TT: Q6.3 U13.5 | length 939.1
  Top Layer w12: Q6.3@1738.51,1147.51 cw(c1718.03,1127.03) 1747,1127.03 cw(c1775.97,1127.03) Q6.3@1755.49,1147.51 ; v2@1742.5,1125.79 ccw(c1735.63,1137.7) 1748.91,1134.14 ; 1744.17,1137.6 cw(c1730.9,1134.05) 1740.63,1124.35 ccw(c1725.27,1139.73) 1747,1139.73 ccw(c1768.73,1139.73) 1753.36,1124.36 cw(c1763.1,1134.05) 1749.83,1137.6 ; 1745.09,1134.14 ccw(c1758.37,1137.7) v2@1751.5,1125.79 ; v2(1747,1118) Q6.3@1747,1163
  Mid-Layer 1 w12: U13.5@1595,542 1747,694 v2(1747,1118) ; U13.5@1595,566 ccw(c1595,623.94) 1635.97,582.97 ccw(c1676.94,542) U13.5@1619,542 ; v2@1740.64,1111.64 cw(c1725.27,1096.27) 1747,1096.27 cw(c1768.73,1096.27) v2@1753.36,1111.64
SPI_CLK: R5.2 U8.6 | length 493.6
  Top Layer w5: R5.2@4043,1643 4178,1643 4316,1505 U8.6@4360,1505 ; R5.2@4049.01,1636.99 cw(c4063.52,1622.48) 4063.52,1643 cw(c4063.52,1663.52) R5.2@4049.01,1649.01 ; R5.2@4052.55,1633.45 cw(c4075.59,1610.41) 4075.59,1643 cw(c4075.59,1675.59) R5.2@4052.55,1652.55 ; U8.6@4335.28,1498.28 ccw(c4319.06,1482.07) 4319.06,1505 ccw(c4319.06,1527.93) U8.6@4335.28,1511.72
SPI_CS_N: R11.2 R15.1 U8.1 | length 578
  Top Layer w5: R11.2@4043,1576 4072,1605 U8.1@4140,1605 v1(4186,1605) ; R11.2@4043,1584.5 ccw(c4043,1605.02) 4057.51,1590.51 ccw(c4072.02,1576) R11.2@4051.5,1576 ; R11.2@4043,1589.5 ccw(c4043,1622.09) 4066.05,1599.05 ccw(c4089.09,1576) R11.2@4056.5,1576 ; U8.1@4115.28,1598.28 ccw(c4099.06,1582.07) 4099.06,1605 ccw(c4099.06,1627.93) U8.1@4115.28,1611.72 ; U8.1@4164.72,1598.28 cw(c4180.94,1582.07) 4180.94,1605 cw(c4180.94,1627.93) U8.1@4164.72,1611.72 ; v1@4179.42,1601.39 ccw(c4168.41,1595.35) 4171.66,1607.48 ccw(c4173.95,1616.01) v1@4180.46,1610.06 ; v1@4179.42,1608.61 cw(c4168.41,1614.65) 4171.66,1602.52 cw(c4173.95,1593.99) v1@4180.46,1599.94 ; v1@4180.7,1599.7 ccw(c4167.89,1586.89) 4167.89,1605 ccw(c4167.89,1623.11) v1@4180.7,1610.3
  Bottom Layer w5: v1(4186,1605) R15.1@4221,1605 ; v1@4186.99,1605 cw(c4186.99,1568.99) R15.1@4212.45,1594.45 ; v1@4189.75,1598.5 cw(c4199.24,1582.06) 4204.16,1600.4 ; v1@4190.6,1610.92 ccw(c4199.95,1622.94) 4203.89,1608.23 ; v1@4191.3,1599.7 cw(c4204.11,1586.89) 4204.11,1605 cw(c4204.11,1623.11) v1@4191.3,1610.3 ; v1@4191.82,1605 ccw(c4191.82,1634.18) R15.1@4212.45,1613.55 ; v1@4192.5,1601.25 cw(c4203.72,1594.77) 4200.37,1607.29 ; v1@4192.5,1608.75 ccw(c4207.42,1617.36) 4202.96,1600.72 ; 4199.06,1605 cw(c4199.06,1581.07) R15.1@4215.99,1597.99 ; 4203.89,1605 ccw(c4203.89,1622.11) R15.1@4215.99,1610.01
SPI_DIN: R6.2 U8.5 | length 562.9
  Top Layer w5: R6.2@4043,1442 4065,1420 ; R6.2@4043.28,1433.5 cw(c4043.9,1415.19) 4056.85,1428.15 cw(c4069.81,1441.1) R6.2@4051.5,1441.72 ; R6.2@4043.45,1428.51 cw(c4044.42,1399.43) 4065,1420 ; R6.2@4056.49,1441.55 ccw(c4085.57,1440.58) 4065,1420 ; 4330.85,1425.85 ccw(c4311.27,1445.42) U8.5@4337.7,1453.66 ; U8.5@4332.93,1452.17 cw(c4302.36,1442.65) 4325,1420 ; 4336.7,1431.7 ccw(c4320.19,1448.2) U8.5@4342.48,1455.15 ; 4342.55,1437.55 ccw(c4329.11,1450.98) U8.5@4347.25,1456.64 ; U8.5@4348.39,1443.39 ccw(c4338.03,1453.76) U8.5@4352.02,1458.12 ; U8.5@4354.24,1449.24 ccw(c4346.94,1456.54) U8.5@4356.8,1459.61 ; U8.5@4360,1455 4325,1420 ; U8.5@4360.09,1455.09 ccw(c4355.86,1459.32) U8.5@4361.57,1461.1 ; 4065,1420 4325,1420
SPI_DOUT: R16.1 U6.P10 | length 1706.4
  Top Layer w5: U6.P10@2774.54,1733.06 v1(2794.22,1752.74) ; U6.P10@2774.54,1739.41 ccw(c2774.54,1754.76) 2785.39,1743.91 ccw(c2796.24,1733.06) U6.P10@2780.89,1733.06 ; U6.P10@2776.89,1739 ccw(c2766.81,1756.46) v1@2786.79,1753.75 ; U6.P10@2780.48,1735.41 cw(c2797.94,1725.33) v1@2795.23,1745.31 ; 2783.77,1742.98 ccw(c2780.32,1748.96) v1@2786.98,1750.77 ; 2784.46,1742.29 cw(c2790.44,1738.84) v1@2792.25,1745.5 ; 2785.58,1744.24 cw(c2796.21,1738.1) v1@2794.56,1750.26 ; 2785.72,1744.1 ccw(c2779.58,1754.73) v1@2791.74,1753.08 ; v1@2786.72,1752.74 cw(c2768.61,1752.74) 2781.42,1739.94 cw(c2794.22,1727.13) v1@2794.22,1745.24 ; v1(3205,1683) 3788,1683 3962,1509 R16.1@3978,1509 ; v1@3210.3,1677.7 cw(c3223.11,1664.89) 3223.11,1683 cw(c3223.11,1701.11) v1@3210.3,1688.3 ; 3927.64,1543.36 ccw(c3978,1593.72) R16.1@3978,1522.5 ; 3936.18,1534.82 ccw(c3978,1576.65) R16.1@3978,1517.5 ; 3944.71,1526.29 ccw(c3978,1559.58) R16.1@3978,1512.5 ; 3953.25,1517.75 ccw(c3978,1542.51) R16.1@3978,1507.5 ; 3961.78,1509.22 ccw(c3978,1525.43) R16.1@3978,1502.5 ; 2786.27,1745.44 ccw(c2780.15,1748.97) 2786.98,1750.8 cw(c2780.15,1748.97) 2786.27,1745.44 ; 2786.92,1744.79 cw(c2790.45,1738.67) 2792.28,1745.5 ccw(c2790.45,1738.67) 2786.92,1744.79
  Bottom Layer w5: v1(2794.22,1752.74) 2833.96,1713 3175,1713 v1(3205,1683) ; v1@3197.5,1683 ccw(c3179.39,1683) 3192.2,1695.8 ccw(c3205,1708.61) v1@3205,1690.5
T4: RN7.2 U6.T4 | length 1901
  Top Layer w5: U6.T4@2853.28,1496.83 3039.17,1496.83 3217,1319 4418,1319 4557.25,1458.25 RN7.2@4573,1458.25 ; U6.T4@2857.77,1492.34 cw(c2868.63,1481.48) 2868.63,1496.83 cw(c2868.63,1512.18) U6.T4@2857.77,1501.33 ; 4545.3,1446.3 cw(c4561.19,1430.41) RN7.2@4561.19,1452.88 ; RN7.2@4553.83,1454.83 cw(c4561.19,1447.48) RN7.2@4561.19,1457.88
T5: RN6.4 U6.T5 | length 1966.1
  Top Layer w5: U6.T5@2853.28,1536.2 3058.8,1536.2 3241,1354 4399,1354 4527,1482 4527,1532 4555.64,1560.64 RN6.4@4573,1560.64 ; U6.T5@2857.77,1531.71 cw(c2868.63,1520.85) 2868.63,1536.2 cw(c2868.63,1551.55) U6.T5@2857.77,1540.7 ; 4542.54,1547.54 cw(c4561.19,1528.88) RN6.4@4561.19,1555.26 ; 4551.07,1556.07 cw(c4561.19,1545.96) RN6.4@4561.19,1560.26
T6: RN6.3 U6.T6 | length 1980.9
  Top Layer w5: U6.T6@2853.28,1575.57 3047.43,1575.57 3253,1370 4385,1370 4509,1494 4509,1545 4556.13,1592.13 RN6.3@4573,1592.13 ; U6.T6@2857.77,1571.08 cw(c2868.63,1560.22) 2868.63,1575.57 cw(c2868.63,1590.92) U6.T6@2857.77,1580.07 ; 4543.38,1579.38 cw(c4561.19,1561.58) RN6.3@4561.19,1586.76 ; 4551.92,1587.92 cw(c4561.19,1578.65) RN6.3@4561.19,1591.76
T7: RN6.1 U6.T7 | length 1996.3
  Top Layer w5: U6.T7@2853.28,1614.94 3066.06,1614.94 3278,1403 4364,1403 4473,1512 4473,1580 4548.12,1655.12 RN6.1@4573,1655.12 ; U6.T7@2857.77,1610.45 cw(c2868.63,1599.59) 2868.63,1614.94 cw(c2868.63,1630.3) U6.T7@2857.77,1619.44 ; RN6.1@4557.39,1651.33 ccw(c4548.22,1642.15) 4548.22,1655.12 ccw(c4548.22,1668.1) RN6.1@4557.39,1658.92
T9: RN5.3 U6.T9 | length 1790.7
  Top Layer w5: U6.T9@2853.28,1693.68 3116.69,1693.68 3144,1721 3941,1721 3977.51,1757.51 RN5.3@4573,1757.51 ; U6.T9@2857.77,1689.19 cw(c2868.63,1678.33) 2868.63,1693.68 cw(c2868.63,1709.04) U6.T9@2857.77,1698.18 ; RN5.3@4557.39,1753.71 ccw(c4548.22,1744.53) 4548.22,1757.51 ccw(c4548.22,1770.48) RN5.3@4557.39,1761.31
T12: RN5.1 U6.T12 | length 1767.8
  Top Layer w5: U6.T12@2853.28,1811.8 3918.3,1811.8 3927,1820.5 RN5.1@4573,1820.5 ; U6.T12@2857.77,1807.3 cw(c2868.63,1796.45) 2868.63,1811.8 cw(c2868.63,1827.15) U6.T12@2857.77,1816.29 ; RN5.1@4557.39,1816.7 ccw(c4548.22,1807.53) 4548.22,1820.5 ccw(c4548.22,1833.47) RN5.1@4557.39,1824.3
T13: RN4.3 U6.T13 | length 1793.9
  Top Layer w5: U6.T13@2853.28,1851.17 3680.17,1851.17 3751.88,1922.88 RN4.3@4573,1922.88 ; U6.T13@2857.77,1846.67 cw(c2868.63,1835.82) 2868.63,1851.17 cw(c2868.63,1866.52) U6.T13@2857.77,1855.66 ; RN4.3@4557.39,1919.08 ccw(c4548.22,1909.91) 4548.22,1922.88 ccw(c4548.22,1935.86) RN4.3@4557.39,1926.68
T14: RN4.2 U6.T14 | length 1790.7
  Top Layer w5: U6.T14@2853.28,1890.54 2889.54,1890.54 2953.38,1954.38 RN4.2@4573,1954.38 ; U6.T14@2857.77,1886.04 cw(c2868.63,1875.19) 2868.63,1890.54 cw(c2868.63,1905.89) U6.T14@2857.77,1895.03 ; RN4.2@4557.39,1950.58 ccw(c4548.22,1941.4) 4548.22,1954.38 ccw(c4548.22,1967.35) RN4.2@4557.39,1958.18
T15: RN3.4 U6.T15 | length 1816.8
  Top Layer w5: U6.T15@2853.28,1929.91 2873.91,1929.91 3000.76,2056.76 RN3.4@4573,2056.76 ; U6.T15@2857.77,1925.41 cw(c2868.63,1914.56) 2868.63,1929.91 cw(c2868.63,1945.26) U6.T15@2857.77,1934.4 ; RN3.4@4557.39,2052.96 ccw(c4548.22,2043.79) 4548.22,2056.76 ccw(c4548.22,2069.74) RN3.4@4557.39,2060.56
TCK: P5.6 R28.1 | length 568.6
  Bottom Layer w5: P5.6@1801.26,3458.37 1839,3420.63 ; P5.6@1801.42,3445.87 cw(c1801.78,3416.96) 1822.23,3437.4 cw(c1842.67,3457.85) P5.6@1813.76,3458.21 ; P5.6@1801.48,3440.87 cw(c1801.99,3400.39) 1830.61,3429.02 cw(c1859.24,3457.64) P5.6@1818.76,3458.15 ; P5.6@1801.54,3435.87 cw(c1802.2,3383.83) 1839,3420.63 ; P5.6@1823.76,3458.09 ccw(c1875.8,3457.43) 1839,3420.63 ; R28.1@1920.5,3222 ccw(c1887.91,3222) 1910.95,3245.05 ccw(c1934,3268.09) R28.1@1934,3235.5 ; R28.1@1925.5,3222 ccw(c1904.98,3222) 1919.49,3236.51 ccw(c1934,3251.02) R28.1@1934,3230.5 ; R28.1@1934,3222 1839,3317 1839,3420.63
TDI: P5.10 R48.1 | length 557.2
  Bottom Layer w5: P5.10@1958.74,3458.37 1997,3420.11 ; P5.10@1958.8,3435.87 cw(c1958.95,3382.07) 1997,3420.11 ; P5.10@1958.79,3440.87 cw(c1958.91,3399.02) 1988.5,3428.61 cw(c2018.09,3458.2) P5.10@1976.24,3458.32 ; P5.10@1958.78,3445.87 cw(c1958.86,3415.98) 1979.99,3437.12 cw(c2001.13,3458.25) P5.10@1971.24,3458.33 ; P5.10@1981.24,3458.31 ccw(c2035.04,3458.16) 1997,3420.11 ; R48.1@2040.5,3222 ccw(c2007.91,3222) 2030.95,3245.05 ccw(c2054,3268.09) R48.1@2054,3235.5 ; R48.1@2045.5,3222 ccw(c2024.98,3222) 2039.49,3236.51 ccw(c2054,3251.02) R48.1@2054,3230.5 ; R48.1@2054,3222 1997,3279 1997,3420.11
TDO: P5.8 R29.1 | length 562.9
  Bottom Layer w5: P5.8@1880,3458.37 1918,3420.37 ; P5.8@1880.1,3445.87 cw(c1880.32,3416.47) 1901.11,3437.26 cw(c1921.9,3458.05) P5.8@1892.5,3458.27 ; P5.8@1880.17,3435.87 cw(c1880.58,3382.95) 1918,3420.37 ; P5.8@1880.13,3440.87 cw(c1880.45,3399.71) 1909.55,3428.82 cw(c1938.66,3457.92) P5.8@1897.5,3458.24 ; P5.8@1902.5,3458.2 ccw(c1955.42,3457.79) 1918,3420.37 ; R29.1@1980.5,3222 ccw(c1947.91,3222) 1970.95,3245.05 ccw(c1994,3268.09) R29.1@1994,3235.5 ; R29.1@1985.5,3222 ccw(c1964.98,3222) 1979.49,3236.51 ccw(c1994,3251.02) R29.1@1994,3230.5 ; R29.1@1994,3222 1918,3298 1918,3420.37
TMS: P5.4 R8.1 | length 581.6
  Bottom Layer w5: P5.4@1722.52,3435.87 cw(c1722.52,3381.55) 1760.93,3419.96 cw(c1799.34,3458.37) P5.4@1745.02,3458.37 ; P5.4@1722.52,3440.87 cw(c1722.52,3398.62) 1752.39,3428.5 cw(c1782.27,3458.37) P5.4@1740.02,3458.37 ; P5.4@1722.52,3445.87 cw(c1722.52,3415.69) 1743.86,3437.03 cw(c1765.2,3458.37) P5.4@1735.02,3458.37 ; P5.4@1722.52,3458.37 1761,3419.89 1761,3335 R8.1@1874,3222 ; R8.1@1860.5,3222 ccw(c1827.91,3222) 1850.95,3245.05 ccw(c1874,3268.09) R8.1@1874,3235.5 ; R8.1@1865.5,3222 ccw(c1844.98,3222) 1859.49,3236.51 ccw(c1874,3251.02) R8.1@1874,3230.5
TXD: R4.1 U4.25 U6.D12 | length 2385.1
  Top Layer w5: U4.25@789.21,2705.73 923.27,2705.73 962,2667 v1(1073.7,2667) R4.1@1107,2700.3 ; U4.25@809.51,2703.74 cw(c814.32,2698.94) 814.32,2705.73 cw(c814.32,2712.53) U4.25@809.51,2707.72 ; v1@1068.4,2661.7 ccw(c1055.59,2648.89) 1055.59,2667 ccw(c1055.59,2685.11) v1@1068.4,2672.3 ; v1@1073.7,2674.5 ccw(c1073.7,2692.61) 1086.5,2679.8 ccw(c1099.31,2667) v1@1081.2,2667 ; R4.1@1093.5,2700.3 cw(c1060.91,2700.3) 1083.95,2677.25 cw(c1107,2654.21) R4.1@1107,2686.8 ; R4.1@1098.5,2700.3 cw(c1077.98,2700.3) 1092.49,2685.79 cw(c1107,2671.28) R4.1@1107,2691.8 ; v1@2360.14,1824.05 cw(c2357.43,1804.07) U6.D12@2374.89,1814.15 ; v1@2360.81,1829 cw(c2359.16,1816.84) 2369.79,1822.98 ; v1@2361.15,1823.98 cw(c2361.15,1805.87) 2373.95,1818.68 cw(c2386.76,1831.48) v1@2368.65,1831.48 ; v1(2361.15,1831.48) U6.D12@2380.83,1811.8 ; v1@2363.63,1831.82 ccw(c2375.79,1833.47) 2369.65,1822.84 ; v1@2368.39,1829.51 ccw(c2375.05,1827.7) 2371.6,1821.72 ; v1@2368.58,1832.49 ccw(c2388.56,1835.2) U6.D12@2378.48,1817.74 ; 2370.91,1821.03 ccw(c2364.93,1817.58) v1@2363.12,1824.24 ; U6.D12@2374.48,1811.8 ccw(c2359.13,1811.8) 2369.98,1822.65 ccw(c2380.83,1833.5) U6.D12@2380.83,1818.15 ; v1@2363.09,1824.24 cw(c2364.92,1817.41) 2368.45,1823.53 ccw(c2364.92,1817.41) v1@2363.09,1824.24 ; v1@2368.39,1829.54 ccw(c2375.22,1827.71) 2369.1,1824.18 cw(c2375.22,1827.71) v1@2368.39,1829.54
  Mid-Layer 1 w5: v1@1073.7,2659.5 cw(c1073.7,2641.39) 1086.5,2654.2 cw(c1099.31,2667) v1@1081.2,2667 ; v1(1073.7,2667) 1908.7,1832 2289,1832 2309,1812 2341.67,1812 v1(2361.15,1831.48) ; v1@2353.65,1831.48 cw(c2335.54,1831.48) 2348.35,1818.68 cw(c2361.15,1805.87) v1@2361.15,1823.98
VBUS: F1.1 J1.1 U2.5 | length 54.6
  Bottom Layer w19: U2.5@801,3082.4 v2(855.6,3082.4)
VCC: C45.1 EC2.1 J2.2 J3.2 P2.2 SW1.3 SW1.6 U1.3 U4.7 U4.8 | length 9207.1
  Top Layer w30: 1722,3182 P2.2@1792,3182 P2.2@1801,3182 ; P2.2@1781.73,3171.73 ccw(c1756.93,3146.93) 1756.93,3182 ccw(c1756.93,3217.07) P2.2@1781.73,3192.27
  Top Layer w40: SW1.3@1240.63,3271.37 ccw(c1210.75,3301.25) 1253,3301.25 ccw(c1295.25,3301.25) SW1.3@1265.37,3271.37 ; SW1.6@1240.63,3461.19 cw(c1210.75,3431.32) 1253,3431.32 cw(c1295.25,3431.32) SW1.6@1265.37,3461.19 ; SW1.3@1253,3259 SW1.6@1253,3473.57
  Top Layer w60: SW1.3@1253,3259 1718,3259 ; 1719,2870 1718,2870 1718,3259 ; J2.2@5001,2721.65 5001,3041 4607,3435 2367,3435 2191,3259 1718,3259
  Mid-Layer 1 w40: J3.2@117,821.65 38,900.65 38,2939 933,2939 SW1.3@1253,3259 SW1.6@1253,3473.57 ; v2(577,2816) 577,2937 ; SW1.3@1235.5,3259 cw(c1193.25,3259) 1223.13,3229.13 cw(c1253,3199.25) SW1.3@1253,3241.5 ; SW1.3@1240.63,3271.37 ccw(c1210.75,3301.25) 1253,3301.25 ccw(c1295.25,3301.25) SW1.3@1265.37,3271.37 ; SW1.6@1240.63,3461.19 cw(c1210.75,3431.32) 1253,3431.32 cw(c1295.25,3431.32) SW1.6@1265.37,3461.19
VGA_HSYNC: R30.2 U6.M14 | length 1503.5
  Top Layer w5: U6.M14@2695.8,1890.54 v1(2715.48,1910.22) ; U6.M14@2695.8,1896.89 ccw(c2695.8,1912.24) 2706.65,1901.39 ccw(c2717.5,1890.54) U6.M14@2702.15,1890.54 ; U6.M14@2698.15,1896.48 ccw(c2688.07,1913.94) v1@2708.05,1911.23 ; U6.M14@2701.74,1892.89 cw(c2719.2,1882.81) v1@2716.49,1902.79 ; 2705.03,1900.46 ccw(c2701.58,1906.44) v1@2708.24,1908.25 ; 2705.72,1899.77 cw(c2711.7,1896.32) v1@2713.51,1902.98 ; 2706.84,1901.72 cw(c2717.47,1895.58) v1@2715.82,1907.74 ; 2706.98,1901.58 ccw(c2700.84,1912.21) v1@2713,1910.56 ; v1@2707.98,1910.22 cw(c2689.87,1910.22) 2702.68,1897.42 cw(c2715.48,1884.61) v1@2715.48,1902.72 ; R30.2@3305.45,2768.45 cw(c3275.17,2738.17) v1@3318,2738.17 ; R30.2@3308.99,2771.99 cw(c3287.24,2750.24) 3318,2750.24 ; v1@3311.61,2736.93 ccw(c3292.71,2748.56) 3314.3,2753.7 ; v1@3312.7,2738.3 ccw(c3299.89,2751.11) 3318,2751.11 ccw(c3336.11,2751.11) v1@3323.3,2738.3 ; 3315.64,2748.08 ccw(c3329.28,2751.33) v1@3321.93,2739.39 ; v1(3318,2733) R30.2@3318,2775 ; 3318,2752.65 cw(c3340.35,2752.65) R30.2@3324.55,2768.45 ; 2707.53,1902.92 ccw(c2701.41,1906.45) 2708.24,1908.28 cw(c2701.41,1906.45) 2707.53,1902.92 ; 2708.18,1902.27 cw(c2711.71,1896.15) 2713.54,1902.98 ccw(c2711.71,1896.15) 2708.18,1902.27
  Mid-Layer 1 w5: v1@2710.18,1915.52 ccw(c2684.05,1941.65) 2721,1941.65 ; v1@2713.71,1911.99 ccw(c2696.12,1929.58) 2721,1929.58 ; v1(2715.48,1910.22) 2721,1915.74 2721,1961 3318,2558 v1(3318,2733) ; v1@3312.7,2727.7 cw(c3299.89,2714.89) 3318,2714.89 cw(c3336.11,2714.89) v1@3323.3,2727.7
VGA_VSYNC: R31.2 U6.L13 | length 1506.6
  Top Layer w5: U6.L13@2656.43,1851.17 v1(2676.11,1870.85) ; U6.L13@2656.43,1857.52 ccw(c2656.43,1872.87) 2667.28,1862.02 ccw(c2678.13,1851.17) U6.L13@2662.78,1851.17 ; U6.L13@2658.78,1857.11 ccw(c2648.7,1874.57) v1@2668.68,1871.86 ; U6.L13@2662.37,1853.52 cw(c2679.83,1843.44) v1@2677.12,1863.42 ; 2665.66,1861.09 ccw(c2662.21,1867.07) v1@2668.87,1868.88 ; 2666.35,1860.4 cw(c2672.33,1856.95) v1@2674.14,1863.61 ; 2667.47,1862.35 cw(c2678.1,1856.21) v1@2676.45,1868.37 ; 2667.61,1862.21 ccw(c2661.47,1872.84) v1@2673.63,1871.19 ; v1@2668.61,1870.85 cw(c2650.5,1870.85) 2663.31,1858.05 cw(c2676.11,1845.24) v1@2676.11,1863.35 ; R31.2@3234.45,2768.45 cw(c3206.58,2740.58) v1@3246,2740.58 ; R31.2@3237.99,2771.99 cw(c3218.65,2752.65) 3246,2752.65 ; v1@3239.77,2737.18 ccw(c3221.64,2749.33) 3242.93,2754.15 ; v1@3240.7,2738.3 ccw(c3227.89,2751.11) 3246,2751.11 ccw(c3264.11,2751.11) v1@3251.3,2738.3 ; 3244.53,2747.09 ccw(c3256.61,2749.82) v1@3250,2739.34 ; v1(3246,2733) R31.2@3246,2776 ; 3246,2750.24 cw(c3271.76,2750.24) R31.2@3253.55,2768.45 ; v1@2668.87,1868.91 cw(c2662.04,1867.08) 2668.16,1863.55 ccw(c2662.04,1867.08) v1@2668.87,1868.91 ; v1@2674.17,1863.61 ccw(c2672.34,1856.78) 2668.81,1862.9 cw(c2672.34,1856.78) v1@2674.17,1863.61
  Mid-Layer 1 w5: v1(2676.11,1870.85) 2695,1889.74 2695,1915 2705,1925 2705,1968 3246,2509 v1(3246,2733) ; v1@2676.11,1878.35 ccw(c2676.11,1896.46) 2688.91,1883.65 ccw(c2701.72,1870.85) v1@2683.61,1870.85 ; v1@3240.7,2727.7 cw(c3227.89,2714.89) 3246,2714.89 cw(c3264.11,2714.89) v1@3251.3,2727.7
VGAD0: RN33.5 U6.P7 | length 2472.2
  Top Layer w5: U6.P7@2774.54,1608.59 cw(c2774.54,1593.24) 2785.39,1604.09 cw(c2796.24,1614.94) U6.P7@2780.89,1614.94 ; U6.P7@2774.54,1614.94 v1(2794.22,1595.26) ; U6.P7@2776.89,1609 cw(c2766.81,1591.54) v1@2786.79,1594.25 ; U6.P7@2780.48,1612.59 ccw(c2797.94,1622.67) v1@2795.23,1602.69 ; 2783.77,1605.02 cw(c2780.32,1599.04) v1@2786.98,1597.23 ; 2784.46,1605.71 ccw(c2790.44,1609.16) v1@2792.25,1602.5 ; 2785.58,1603.76 ccw(c2796.21,1609.9) v1@2794.56,1597.74 ; 2785.72,1603.9 cw(c2779.58,1593.27) v1@2791.74,1594.92 ; v1@2786.72,1595.26 ccw(c2768.61,1595.26) 2781.42,1608.06 ccw(c2794.22,1620.87) v1@2794.22,1602.76 ; v1@4486.21,2544.79 ccw(c4473.41,2557.59) 4491.51,2557.59 ccw(c4509.62,2557.59) v1@4496.82,2544.79 ; RN33.5@4487.71,2555.24 cw(c4478.54,2546.07) 4491.51,2546.07 cw(c4504.49,2546.07) RN33.5@4495.31,2555.24 ; v1@4488.89,2546.52 ccw(c4487.96,2549.01) 4490.54,2549.7 ccw(c4494.62,2550.8) v1@4493.5,2546.72 ; v1@4489.52,2546.72 ccw(c4488.4,2550.8) 4492.49,2549.7 ccw(c4495.06,2549.01) v1@4494.13,2546.52 ; v1(4491.51,2539.49) RN33.5@4491.51,2570.85 ; 2786.27,1602.56 cw(c2780.15,1599.03) 2786.98,1597.2 ccw(c2780.15,1599.03) 2786.27,1602.56 ; 2786.92,1603.21 ccw(c2790.45,1609.33) 2792.28,1602.5 cw(c2790.45,1609.33) 2786.92,1603.21
  Mid-Layer 1 w5: v1@2792.45,1593.49 ccw(c2805.71,1606.75) 2805.71,1588 ; v1(2794.22,1595.26) 2801.48,1588 3236,1588 4088,2440 4392.02,2440 v1(4491.51,2539.49) ; v1@2795.99,1597.03 ccw(c2817.78,1618.82) 2817.78,1588 ; v1@2799.52,1600.56 ccw(c2829.85,1630.89) 2829.85,1588 ; v1@4484.01,2539.49 cw(c4465.91,2539.49) 4478.71,2526.68 cw(c4491.51,2513.88) v1@4491.51,2531.99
